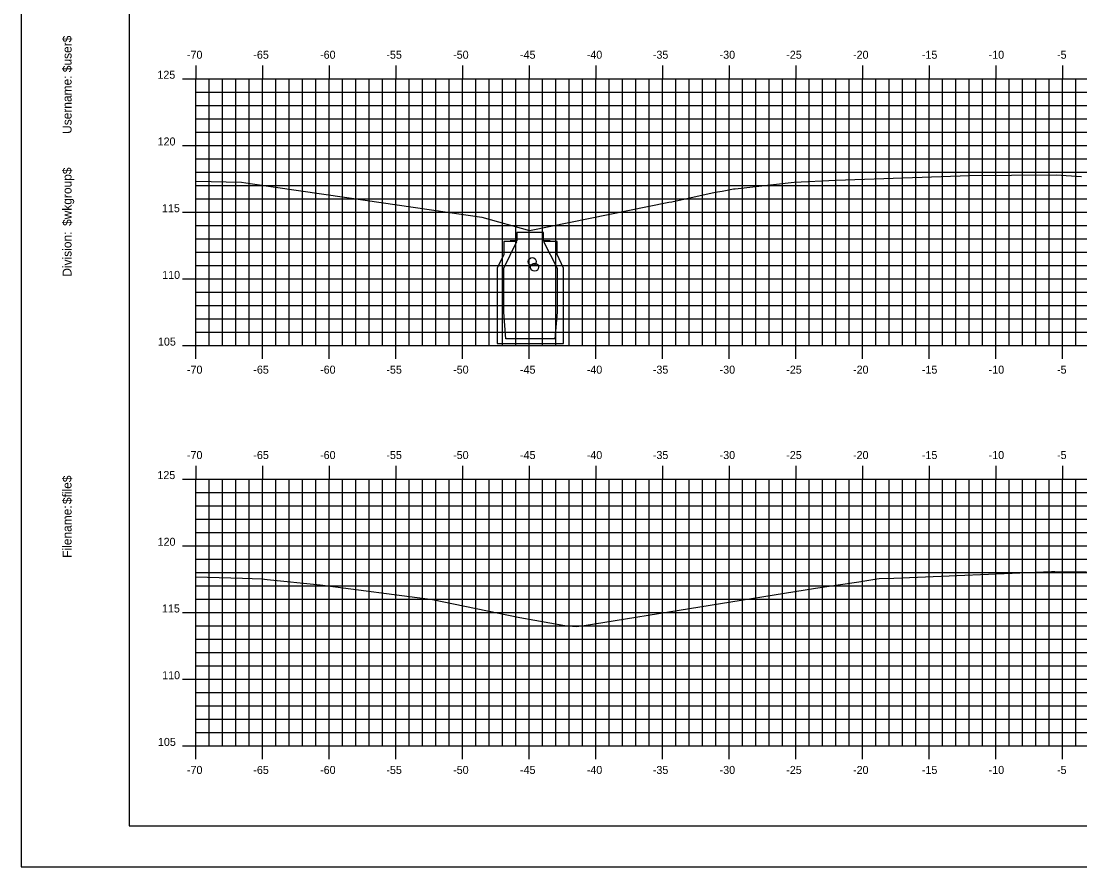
# Model space of a CAD drawing. Extents: x 853734 to 853906, y 365624 to 365734.
# Drawn here: x 853734.2 to 853813.6, y 365624 to 365687.3 of the extents above; entities that cross this region are included whole.
import ezdxf

# ---------------------------------------------------------------- set-up
doc = ezdxf.new("R2010")
doc.units = 0
for name, color, linetype in [('BORDER', 7, 'Continuous'), ('H_V ANNOTATION', 7, 'Continuous'), ('M_Roadway_Centerline', 7, 'Continuous'), ('MAJOR', 7, 'Continuous'), ('MINOR', 7, 'Continuous'), ('PLOT BOUNDARY', 7, 'Continuous'), ('S_Drainage_CB', 7, 'Continuous'), ('S_Drainage_Invert', 7, 'Continuous'), ('S_Roadway_Centerline', 7, 'Continuous')]:
    doc.layers.add(name, color=color, linetype=linetype)

msp = doc.modelspace()

# ---------------------------------------------------------------- linework, layer by layer
at = {"layer": 'BORDER'}
msp.add_lwpolyline([(853742.331, 365627.027), (853902.331, 365627.027), (853902.331, 365732.027), (853742.331, 365732.027)], close=True, dxfattribs=at)
at = {"layer": 'MAJOR'}
for p, q in [((853747.331, 365684.029), (853747.331, 365683.027)), ((853752.331, 365684.029), (853752.331, 365683.027)), ((853757.331, 365684.029), (853757.331, 365683.027)), ((853762.331, 365684.029), (853762.331, 365683.027)), ((853767.331, 365684.029), (853767.331, 365683.027)), ((853772.331, 365684.029), (853772.331, 365683.027)), ((853777.331, 365684.029), (853777.331, 365683.027)), ((853782.331, 365684.029), (853782.331, 365683.027)), ((853787.331, 365684.029), (853787.331, 365683.027)), ((853792.331, 365684.029), (853792.331, 365683.027)), ((853797.331, 365684.029), (853797.331, 365683.027)), ((853802.331, 365684.029), (853802.331, 365683.027)), ((853807.331, 365684.029), (853807.331, 365683.027)), ((853812.331, 365684.029), (853812.331, 365683.027)), ((853746.329, 365683.027), (853747.331, 365683.027)), ((853747.331, 365683.027), (853887.331, 365683.027)), ((853747.331, 365663.027), (853747.331, 365683.027)), ((853747.331, 365663.027), (853747.331, 365683.027)), ((853747.331, 365683.027), (853887.331, 365683.027)), ((853752.331, 365663.027), (853752.331, 365683.027)), ((853757.331, 365663.027), (853757.331, 365683.027)), ((853762.331, 365663.027), (853762.331, 365683.027)), ((853767.331, 365663.027), (853767.331, 365683.027)), ((853772.331, 365663.027), (853772.331, 365683.027)), ((853777.331, 365663.027), (853777.331, 365683.027)), ((853782.331, 365663.027), (853782.331, 365683.027)), ((853787.331, 365663.027), (853787.331, 365683.027)), ((853792.331, 365663.027), (853792.331, 365683.027)), ((853797.331, 365663.027), (853797.331, 365683.027)), ((853802.331, 365663.027), (853802.331, 365683.027)), ((853807.331, 365663.027), (853807.331, 365683.027)), ((853812.331, 365663.027), (853812.331, 365683.027)), ((853746.329, 365678.027), (853747.331, 365678.027)), ((853747.331, 365678.027), (853887.331, 365678.027)), ((853746.329, 365673.027), (853747.331, 365673.027)), ((853747.331, 365673.027), (853887.331, 365673.027)), ((853746.329, 365668.027), (853747.331, 365668.027)), ((853747.331, 365668.027), (853887.331, 365668.027)), ((853746.329, 365663.027), (853747.331, 365663.027)), ((853747.331, 365663.027), (853887.331, 365663.027)), ((853747.331, 365663.027), (853887.331, 365663.027)), ((853747.331, 365662.025), (853747.331, 365663.027)), ((853752.331, 365662.025), (853752.331, 365663.027)), ((853757.331, 365662.025), (853757.331, 365663.027)), ((853762.331, 365662.025), (853762.331, 365663.027)), ((853767.331, 365662.025), (853767.331, 365663.027)), ((853772.331, 365662.025), (853772.331, 365663.027)), ((853777.331, 365662.025), (853777.331, 365663.027)), ((853782.331, 365662.025), (853782.331, 365663.027)), ((853787.331, 365662.025), (853787.331, 365663.027)), ((853792.331, 365662.025), (853792.331, 365663.027)), ((853797.331, 365662.025), (853797.331, 365663.027)), ((853802.331, 365662.025), (853802.331, 365663.027)), ((853807.331, 365662.025), (853807.331, 365663.027)), ((853812.331, 365662.025), (853812.331, 365663.027)), ((853747.331, 365654.029), (853747.331, 365653.027)), ((853752.331, 365654.029), (853752.331, 365653.027)), ((853757.331, 365654.029), (853757.331, 365653.027)), ((853762.331, 365654.029), (853762.331, 365653.027)), ((853767.331, 365654.029), (853767.331, 365653.027)), ((853772.331, 365654.029), (853772.331, 365653.027)), ((853777.331, 365654.029), (853777.331, 365653.027)), ((853782.331, 365654.029), (853782.331, 365653.027)), ((853787.331, 365654.029), (853787.331, 365653.027)), ((853792.331, 365654.029), (853792.331, 365653.027)), ((853797.331, 365654.029), (853797.331, 365653.027)), ((853802.331, 365654.029), (853802.331, 365653.027)), ((853807.331, 365654.029), (853807.331, 365653.027)), ((853812.331, 365654.029), (853812.331, 365653.027)), ((853746.329, 365653.027), (853747.331, 365653.027)), ((853747.331, 365653.027), (853887.331, 365653.027)), ((853747.331, 365633.027), (853747.331, 365653.027)), ((853747.331, 365633.027), (853747.331, 365653.027)), ((853747.331, 365653.027), (853887.331, 365653.027)), ((853752.331, 365633.027), (853752.331, 365653.027)), ((853757.331, 365633.027), (853757.331, 365653.027)), ((853762.331, 365633.027), (853762.331, 365653.027)), ((853767.331, 365633.027), (853767.331, 365653.027)), ((853772.331, 365633.027), (853772.331, 365653.027)), ((853777.331, 365633.027), (853777.331, 365653.027)), ((853782.331, 365633.027), (853782.331, 365653.027)), ((853787.331, 365633.027), (853787.331, 365653.027)), ((853792.331, 365633.027), (853792.331, 365653.027)), ((853797.331, 365633.027), (853797.331, 365653.027)), ((853802.331, 365633.027), (853802.331, 365653.027)), ((853807.331, 365633.027), (853807.331, 365653.027)), ((853812.331, 365633.027), (853812.331, 365653.027)), ((853746.329, 365648.027), (853747.331, 365648.027)), ((853747.331, 365648.027), (853887.331, 365648.027)), ((853746.329, 365643.027), (853747.331, 365643.027)), ((853747.331, 365643.027), (853887.331, 365643.027)), ((853746.329, 365638.027), (853747.331, 365638.027)), ((853747.331, 365638.027), (853887.331, 365638.027)), ((853746.329, 365633.027), (853747.331, 365633.027)), ((853747.331, 365633.027), (853887.331, 365633.027)), ((853747.331, 365633.027), (853887.331, 365633.027)), ((853747.331, 365632.025), (853747.331, 365633.027)), ((853752.331, 365632.025), (853752.331, 365633.027)), ((853757.331, 365632.025), (853757.331, 365633.027)), ((853762.331, 365632.025), (853762.331, 365633.027)), ((853767.331, 365632.025), (853767.331, 365633.027)), ((853772.331, 365632.025), (853772.331, 365633.027)), ((853777.331, 365632.025), (853777.331, 365633.027)), ((853782.331, 365632.025), (853782.331, 365633.027)), ((853787.331, 365632.025), (853787.331, 365633.027)), ((853792.331, 365632.025), (853792.331, 365633.027)), ((853797.331, 365632.025), (853797.331, 365633.027)), ((853802.331, 365632.025), (853802.331, 365633.027)), ((853807.331, 365632.025), (853807.331, 365633.027)), ((853812.331, 365632.025), (853812.331, 365633.027))]:
    msp.add_line(p, q, dxfattribs=at)
at = {"layer": 'MINOR'}
for p, q in [((853748.331, 365663.027), (853748.331, 365683.027)), ((853749.331, 365663.027), (853749.331, 365683.027)), ((853750.331, 365663.027), (853750.331, 365683.027)), ((853751.331, 365663.027), (853751.331, 365683.027)), ((853753.331, 365663.027), (853753.331, 365683.027)), ((853754.331, 365663.027), (853754.331, 365683.027)), ((853755.331, 365663.027), (853755.331, 365683.027)), ((853756.331, 365663.027), (853756.331, 365683.027)), ((853758.331, 365663.027), (853758.331, 365683.027)), ((853759.331, 365663.027), (853759.331, 365683.027)), ((853760.331, 365663.027), (853760.331, 365683.027)), ((853761.331, 365663.027), (853761.331, 365683.027)), ((853763.331, 365663.027), (853763.331, 365683.027)), ((853764.331, 365663.027), (853764.331, 365683.027)), ((853765.331, 365663.027), (853765.331, 365683.027)), ((853766.331, 365663.027), (853766.331, 365683.027)), ((853768.331, 365663.027), (853768.331, 365683.027)), ((853769.331, 365663.027), (853769.331, 365683.027)), ((853770.331, 365663.027), (853770.331, 365683.027)), ((853771.331, 365663.027), (853771.331, 365683.027)), ((853773.331, 365663.027), (853773.331, 365683.027)), ((853774.331, 365663.027), (853774.331, 365683.027)), ((853775.331, 365663.027), (853775.331, 365683.027)), ((853776.331, 365663.027), (853776.331, 365683.027)), ((853778.331, 365663.027), (853778.331, 365683.027)), ((853779.331, 365663.027), (853779.331, 365683.027)), ((853780.331, 365663.027), (853780.331, 365683.027)), ((853781.331, 365663.027), (853781.331, 365683.027)), ((853783.331, 365663.027), (853783.331, 365683.027)), ((853784.331, 365663.027), (853784.331, 365683.027)), ((853785.331, 365663.027), (853785.331, 365683.027)), ((853786.331, 365663.027), (853786.331, 365683.027)), ((853788.331, 365663.027), (853788.331, 365683.027)), ((853789.331, 365663.027), (853789.331, 365683.027)), ((853790.331, 365663.027), (853790.331, 365683.027)), ((853791.331, 365663.027), (853791.331, 365683.027)), ((853793.331, 365663.027), (853793.331, 365683.027)), ((853794.331, 365663.027), (853794.331, 365683.027)), ((853795.331, 365663.027), (853795.331, 365683.027)), ((853796.331, 365663.027), (853796.331, 365683.027)), ((853798.331, 365663.027), (853798.331, 365683.027)), ((853799.331, 365663.027), (853799.331, 365683.027)), ((853800.331, 365663.027), (853800.331, 365683.027)), ((853801.331, 365663.027), (853801.331, 365683.027)), ((853803.331, 365663.027), (853803.331, 365683.027)), ((853804.331, 365663.027), (853804.331, 365683.027)), ((853805.331, 365663.027), (853805.331, 365683.027)), ((853806.331, 365663.027), (853806.331, 365683.027)), ((853808.331, 365663.027), (853808.331, 365683.027)), ((853809.331, 365663.027), (853809.331, 365683.027)), ((853810.331, 365663.027), (853810.331, 365683.027)), ((853811.331, 365663.027), (853811.331, 365683.027)), ((853813.331, 365663.027), (853813.331, 365683.027)), ((853747.331, 365682.027), (853887.331, 365682.027)), ((853747.331, 365682.027), (853748.333, 365682.027)), ((853747.331, 365681.027), (853887.331, 365681.027)), ((853747.331, 365681.027), (853748.333, 365681.027)), ((853747.331, 365680.027), (853887.331, 365680.027)), ((853747.331, 365680.027), (853748.333, 365680.027)), ((853747.331, 365679.027), (853887.331, 365679.027)), ((853747.331, 365679.027), (853748.333, 365679.027)), ((853747.331, 365677.027), (853887.331, 365677.027)), ((853747.331, 365677.027), (853748.333, 365677.027)), ((853747.331, 365676.027), (853887.331, 365676.027)), ((853747.331, 365676.027), (853748.333, 365676.027)), ((853747.331, 365675.027), (853887.331, 365675.027)), ((853747.331, 365675.027), (853748.333, 365675.027)), ((853747.331, 365674.027), (853887.331, 365674.027)), ((853747.331, 365674.027), (853748.333, 365674.027)), ((853747.331, 365672.027), (853887.331, 365672.027)), ((853747.331, 365672.027), (853748.333, 365672.027)), ((853747.331, 365671.027), (853887.331, 365671.027)), ((853747.331, 365671.027), (853748.333, 365671.027)), ((853747.331, 365670.027), (853887.331, 365670.027)), ((853747.331, 365670.027), (853748.333, 365670.027)), ((853747.331, 365669.027), (853887.331, 365669.027)), ((853747.331, 365669.027), (853748.333, 365669.027)), ((853747.331, 365667.027), (853887.331, 365667.027)), ((853747.331, 365667.027), (853748.333, 365667.027)), ((853747.331, 365666.027), (853887.331, 365666.027)), ((853747.331, 365666.027), (853748.333, 365666.027)), ((853747.331, 365665.027), (853887.331, 365665.027)), ((853747.331, 365665.027), (853748.333, 365665.027)), ((853747.331, 365664.027), (853887.331, 365664.027)), ((853747.331, 365664.027), (853748.333, 365664.027)), ((853748.331, 365633.027), (853748.331, 365653.027)), ((853749.331, 365633.027), (853749.331, 365653.027)), ((853750.331, 365633.027), (853750.331, 365653.027)), ((853751.331, 365633.027), (853751.331, 365653.027)), ((853753.331, 365633.027), (853753.331, 365653.027)), ((853754.331, 365633.027), (853754.331, 365653.027)), ((853755.331, 365633.027), (853755.331, 365653.027)), ((853756.331, 365633.027), (853756.331, 365653.027)), ((853758.331, 365633.027), (853758.331, 365653.027)), ((853759.331, 365633.027), (853759.331, 365653.027)), ((853760.331, 365633.027), (853760.331, 365653.027)), ((853761.331, 365633.027), (853761.331, 365653.027)), ((853763.331, 365633.027), (853763.331, 365653.027)), ((853764.331, 365633.027), (853764.331, 365653.027)), ((853765.331, 365633.027), (853765.331, 365653.027)), ((853766.331, 365633.027), (853766.331, 365653.027)), ((853768.331, 365633.027), (853768.331, 365653.027)), ((853769.331, 365633.027), (853769.331, 365653.027)), ((853770.331, 365633.027), (853770.331, 365653.027)), ((853771.331, 365633.027), (853771.331, 365653.027)), ((853773.331, 365633.027), (853773.331, 365653.027)), ((853774.331, 365633.027), (853774.331, 365653.027)), ((853775.331, 365633.027), (853775.331, 365653.027)), ((853776.331, 365633.027), (853776.331, 365653.027)), ((853778.331, 365633.027), (853778.331, 365653.027)), ((853779.331, 365633.027), (853779.331, 365653.027)), ((853780.331, 365633.027), (853780.331, 365653.027)), ((853781.331, 365633.027), (853781.331, 365653.027)), ((853783.331, 365633.027), (853783.331, 365653.027)), ((853784.331, 365633.027), (853784.331, 365653.027)), ((853785.331, 365633.027), (853785.331, 365653.027)), ((853786.331, 365633.027), (853786.331, 365653.027)), ((853788.331, 365633.027), (853788.331, 365653.027)), ((853789.331, 365633.027), (853789.331, 365653.027)), ((853790.331, 365633.027), (853790.331, 365653.027)), ((853791.331, 365633.027), (853791.331, 365653.027)), ((853793.331, 365633.027), (853793.331, 365653.027)), ((853794.331, 365633.027), (853794.331, 365653.027)), ((853795.331, 365633.027), (853795.331, 365653.027)), ((853796.331, 365633.027), (853796.331, 365653.027)), ((853798.331, 365633.027), (853798.331, 365653.027)), ((853799.331, 365633.027), (853799.331, 365653.027)), ((853800.331, 365633.027), (853800.331, 365653.027)), ((853801.331, 365633.027), (853801.331, 365653.027)), ((853803.331, 365633.027), (853803.331, 365653.027)), ((853804.331, 365633.027), (853804.331, 365653.027)), ((853805.331, 365633.027), (853805.331, 365653.027)), ((853806.331, 365633.027), (853806.331, 365653.027)), ((853808.331, 365633.027), (853808.331, 365653.027)), ((853809.331, 365633.027), (853809.331, 365653.027)), ((853810.331, 365633.027), (853810.331, 365653.027)), ((853811.331, 365633.027), (853811.331, 365653.027)), ((853813.331, 365633.027), (853813.331, 365653.027)), ((853747.331, 365652.027), (853887.331, 365652.027)), ((853747.331, 365652.027), (853748.333, 365652.027)), ((853747.331, 365651.027), (853887.331, 365651.027)), ((853747.331, 365651.027), (853748.333, 365651.027)), ((853747.331, 365650.027), (853887.331, 365650.027)), ((853747.331, 365650.027), (853748.333, 365650.027)), ((853747.331, 365649.027), (853887.331, 365649.027)), ((853747.331, 365649.027), (853748.333, 365649.027)), ((853747.331, 365647.027), (853887.331, 365647.027)), ((853747.331, 365647.027), (853748.333, 365647.027)), ((853747.331, 365646.027), (853887.331, 365646.027)), ((853747.331, 365646.027), (853748.333, 365646.027)), ((853747.331, 365645.027), (853887.331, 365645.027)), ((853747.331, 365645.027), (853748.333, 365645.027)), ((853747.331, 365644.027), (853887.331, 365644.027)), ((853747.331, 365644.027), (853748.333, 365644.027)), ((853747.331, 365642.027), (853887.331, 365642.027)), ((853747.331, 365642.027), (853748.333, 365642.027)), ((853747.331, 365641.027), (853887.331, 365641.027)), ((853747.331, 365641.027), (853748.333, 365641.027)), ((853747.331, 365640.027), (853887.331, 365640.027)), ((853747.331, 365640.027), (853748.333, 365640.027)), ((853747.331, 365639.027), (853887.331, 365639.027)), ((853747.331, 365639.027), (853748.333, 365639.027)), ((853747.331, 365637.027), (853887.331, 365637.027)), ((853747.331, 365637.027), (853748.333, 365637.027)), ((853747.331, 365636.027), (853887.331, 365636.027)), ((853747.331, 365636.027), (853748.333, 365636.027)), ((853747.331, 365635.027), (853887.331, 365635.027)), ((853747.331, 365635.027), (853748.333, 365635.027)), ((853747.331, 365634.027), (853887.331, 365634.027)), ((853747.331, 365634.027), (853748.333, 365634.027))]:
    msp.add_line(p, q, dxfattribs=at)
at = {"layer": 'PLOT BOUNDARY'}
msp.add_lwpolyline([(853734.238, 365623.968), (853904.238, 365623.968), (853904.238, 365733.968), (853734.238, 365733.968)], close=True, dxfattribs=at)
at = {"layer": 'S_Drainage_CB'}
for p, q in [((853771.409, 365670.84), (853770.425, 365670.84)), ((853770.425, 365670.84), (853770.425, 365669.856)), ((853770.425, 365668.839), (853771.409, 365670.84)), ((853774.427, 365670.84), (853773.41, 365670.84)), ((853773.41, 365670.84), (853774.427, 365668.839)), ((853774.427, 365669.856), (853774.427, 365670.84)), ((853770.425, 365669.856), (853769.933, 365668.839)), ((853774.919, 365668.839), (853774.427, 365669.856)), ((853769.933, 365668.839), (853769.933, 365663.196)), ((853770.425, 365665.525), (853770.425, 365668.839)), ((853774.427, 365668.839), (853774.427, 365665.525)), ((853774.919, 365663.196), (853774.919, 365668.839)), ((853770.589, 365663.524), (853770.425, 365665.525)), ((853774.427, 365665.525), (853774.263, 365663.524)), ((853769.933, 365663.196), (853774.919, 365663.196)), ((853774.263, 365663.524), (853770.589, 365663.524))]:
    msp.add_line(p, q, dxfattribs=at)
msp.add_lwpolyline([(853773.902, 365670.882), (853773.41, 365670.882), (853773.41, 365671.505), (853771.409, 365671.505), (853771.409, 365670.882), (853770.917, 365670.882)], dxfattribs=at)
at = {"layer": 'S_Drainage_Invert'}
for centre in [(853772.569, 365669.325), (853772.744, 365668.905)]:
    msp.add_circle(centre, 0.3, dxfattribs=at)
at = {"layer": 'S_Roadway_Centerline'}
for points in [[(853747.331, 365675.355), (853750.766, 365675.288), (853751.408, 365675.167), (853758.672, 365674.13), (853768.784, 365672.666), (853772.361, 365671.646), (853782.803, 365673.769), (853783.024, 365673.803), (853786.281, 365674.522), (853786.806, 365674.603), (853787.657, 365674.775), (853787.777, 365674.789), (853792.205, 365675.28), (853795.339, 365675.416), (853803.245, 365675.702), (853805.368, 365675.767), (853808.5, 365675.807), (853811.863, 365675.837), (853813.755, 365675.697)], [(853747.331, 365645.708), (853750.848, 365645.591), (853752.29, 365645.539), (853752.681, 365645.501), (853756.656, 365645.112), (853765.089, 365644.005), (853771.638, 365642.663), (853775.009, 365642.061), (853775.856, 365641.966), (853776.454, 365642.052), (853793.814, 365644.851), (853797.066, 365645.334), (853798.409, 365645.555), (853798.594, 365645.565), (853799.671, 365645.604), (853811.51, 365646.103), (853811.758, 365646.1), (853814.129, 365646.084)]]:
    msp.add_lwpolyline(points, dxfattribs=at)

# ---------------------------------------------------------------- texts
at = {"layer": 'BORDER'}
for s, p in [('$user$', (853738.016, 365683.518)), ('Username:', (853738.016, 365678.895)), ('$wkgroup$', (853738.016, 365671.996)), ('Division:', (853738.016, 365668.193)), ('$file$', (853738.016, 365651.152)), ('Filename:', (853738.016, 365647.125))]:
    msp.add_text(s, height=0.6696, rotation=90, dxfattribs=at).set_placement(p)
at = {"layer": 'H_V ANNOTATION'}
for s, p in [('-70', (853746.673, 365684.527)), ('-65', (853751.649, 365684.527)), ('-60', (853756.657, 365684.527)), ('-55', (853761.627, 365684.527)), ('-50', (853766.635, 365684.527)), ('-45', (853771.649, 365684.527)), ('-40', (853776.657, 365684.527)), ('-35', (853781.611, 365684.527)), ('-30', (853786.619, 365684.527)), ('-25', (853791.617, 365684.527)), ('-20', (853796.625, 365684.527)), ('-15', (853801.788, 365684.527)), ('-10', (853806.796, 365684.527)), ('-5', (853811.922, 365684.527)), ('125', (853744.456, 365683.027)), ('120', (853744.472, 365678.027)), ('115', (853744.798, 365673.027)), ('110', (853744.814, 365668.027)), ('105', (853744.498, 365663.027)), ('-70', (853746.673, 365660.927)), ('-65', (853751.649, 365660.927)), ('-60', (853756.657, 365660.927)), ('-55', (853761.627, 365660.927)), ('-50', (853766.635, 365660.927)), ('-45', (853771.649, 365660.927)), ('-40', (853776.657, 365660.927)), ('-35', (853781.611, 365660.927)), ('-30', (853786.619, 365660.927)), ('-25', (853791.617, 365660.927)), ('-20', (853796.625, 365660.927)), ('-15', (853801.788, 365660.927)), ('-10', (853806.796, 365660.927)), ('-5', (853811.922, 365660.927)), ('-70', (853746.673, 365654.527)), ('-65', (853751.649, 365654.527)), ('-60', (853756.657, 365654.527)), ('-55', (853761.627, 365654.527)), ('-50', (853766.635, 365654.527)), ('-45', (853771.649, 365654.527)), ('-40', (853776.657, 365654.527)), ('-35', (853781.611, 365654.527)), ('-30', (853786.619, 365654.527)), ('-25', (853791.617, 365654.527)), ('-20', (853796.625, 365654.527)), ('-15', (853801.788, 365654.527)), ('-10', (853806.796, 365654.527)), ('-5', (853811.922, 365654.527)), ('125', (853744.456, 365653.027)), ('120', (853744.472, 365648.027)), ('115', (853744.798, 365643.027)), ('110', (853744.814, 365638.027)), ('105', (853744.498, 365633.027)), ('-70', (853746.673, 365630.927)), ('-65', (853751.649, 365630.927)), ('-60', (853756.657, 365630.927)), ('-55', (853761.627, 365630.927)), ('-50', (853766.635, 365630.927)), ('-45', (853771.649, 365630.927)), ('-40', (853776.657, 365630.927)), ('-35', (853781.611, 365630.927)), ('-30', (853786.619, 365630.927)), ('-25', (853791.617, 365630.927)), ('-20', (853796.625, 365630.927)), ('-15', (853801.788, 365630.927)), ('-10', (853806.796, 365630.927)), ('-5', (853811.922, 365630.927))]:
    msp.add_text(s, height=0.6, dxfattribs=at).set_placement(p)
at = {"layer": 'M_Roadway_Centerline'}
for s, p in [('C', (853805.363, 365675.767)), ('L', (853805.368, 365675.759)), ('C', (853811.505, 365646.103)), ('L', (853811.51, 365646.096))]:
    msp.add_text(s, height=0.0146, dxfattribs=at).set_placement(p)
at = {"layer": 'MAJOR'}
for p in [(853747.327, 365663.027), (853747.327, 365633.027)]:
    msp.add_text('-', height=0.006, dxfattribs=at).set_placement(p)

doc.saveas('drawing.dxf')
